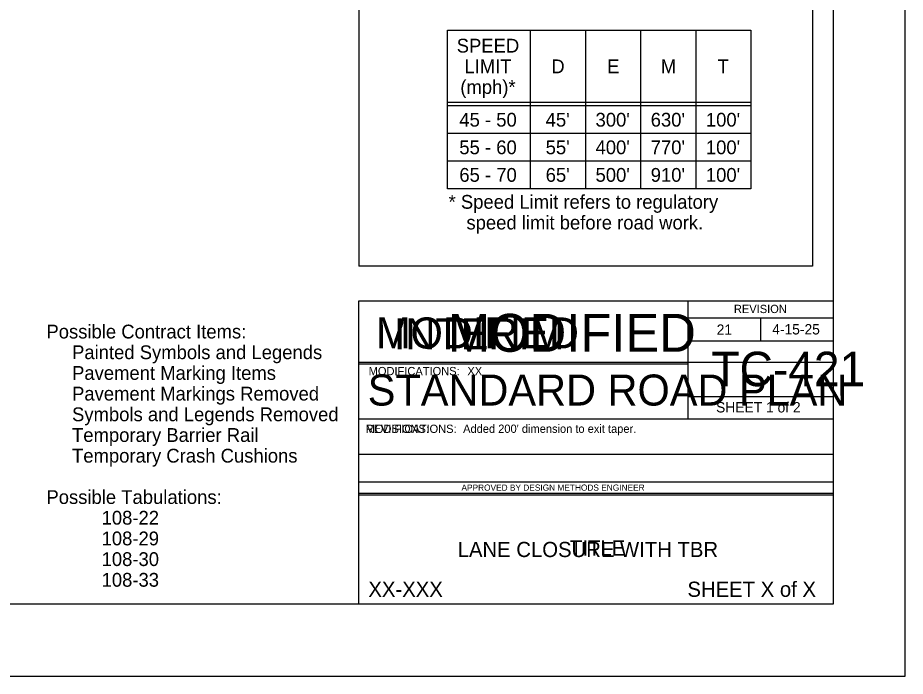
# Model space of a CAD drawing. Extents: x -2135039 to 114557, y -2139150 to -409929.
# Drawn here: x -2132982 to -2131695, y -2139150 to -2138196 of the extents above; entities that cross this region are included whole.
import ezdxf

# ---------------------------------------------------------------- set-up
doc = ezdxf.new("R2010")
doc.units = 0
for name, color, linetype in [('dsnDOTLogo', 7, 'Continuous'), ('dsnNonPlotable', 7, 'Continuous'), ('dsnStdBlock', 7, 'Continuous'), ('dsnstdblockInterim', 7, 'Continuous'), ('dsnStdLogo', 7, 'Continuous'), ('dsnstdModifiedBlock', 7, 'Continuous'), ('dsnStdTable', 7, 'Continuous'), ('Level 1', 7, 'Continuous'), ('StdNote', 7, 'Continuous')]:
    doc.layers.add(name, color=color, linetype=linetype)

msp = doc.modelspace()

# ---------------------------------------------------------------- linework, layer by layer
at = {"layer": 'dsnDOTLogo'}
msp.add_lwpolyline([(-2135038.9, -2139150.4), (-2131694.9, -2139150.4), (-2131694.9, -2136566.4), (-2135038.9, -2136566.4)], close=True, dxfattribs=at)
at = {"layer": 'dsnNonPlotable'}
for p, q in [((-2132487.5, -2137085.9), (-2132487.5, -2138555.9)), ((-2131829.4, -2137085.9), (-2131829.4, -2138555.9)), ((-2131829.4, -2138555.9), (-2132487.5, -2138555.9))]:
    msp.add_line(p, q, dxfattribs=at)
at = {"layer": 'dsnStdLogo'}
for p, q in [((-2132010.4, -2138605.9), (-2132010.4, -2138697.3)), ((-2132010.4, -2138630.9), (-2131799.4, -2138630.9)), ((-2131904.9, -2138630.9), (-2131904.9, -2138664.1)), ((-2132010.4, -2138664.1), (-2131799.4, -2138664.1)), ((-2132487.5, -2138697.3), (-2132010.4, -2138697.3)), ((-2132010.4, -2138697.3), (-2132010.4, -2138777.3)), ((-2131799.4, -2138745.1), (-2132010.4, -2138745.1)), ((-2132487.5, -2138777.3), (-2131799.4, -2138777.3)), ((-2132487.5, -2138828.3), (-2131799.4, -2138828.3)), ((-2132487.5, -2138868.3), (-2131799.4, -2138868.3)), ((-2132487.5, -2138887.3), (-2131799.4, -2138887.3))]:
    msp.add_line(p, q, dxfattribs=at)
msp.add_lwpolyline([(-2132487.5, -2138605.9), (-2131799.4, -2138605.9), (-2131799.4, -2139045.9), (-2132487.5, -2139045.9)], close=True, dxfattribs=at)
at = {"layer": 'dsnstdModifiedBlock'}
for p, q in [((-2132487.5, -2138695), (-2131799.4, -2138695)), ((-2132487.5, -2138885), (-2131799.4, -2138885))]:
    msp.add_line(p, q, dxfattribs=at)
msp.add_lwpolyline([(-2132487.5, -2138605.9), (-2131799.4, -2138605.9), (-2131799.4, -2139045.9), (-2132487.5, -2139045.9)], close=True, dxfattribs=at)
at = {"layer": 'dsnStdTable'}
for p, q in [((-2132358.8, -2138443.4), (-2132358.8, -2138213.6)), ((-2132358.8, -2138213.6), (-2131918.8, -2138213.6)), ((-2132238.8, -2138213.6), (-2132238.8, -2138443.4)), ((-2132158.8, -2138213.6), (-2132158.8, -2138443.4)), ((-2132078.8, -2138213.6), (-2132078.8, -2138443.4)), ((-2131998.8, -2138213.6), (-2131998.8, -2138443.4)), ((-2131918.8, -2138213.6), (-2131918.8, -2138443.4)), ((-2131918.8, -2138318.4), (-2132358.8, -2138318.4)), ((-2131918.8, -2138323.4), (-2132358.8, -2138323.4)), ((-2131918.8, -2138363.4), (-2132358.8, -2138363.4)), ((-2131918.8, -2138403.4), (-2132358.8, -2138403.4)), ((-2131918.8, -2138443.4), (-2132358.8, -2138443.4))]:
    msp.add_line(p, q, dxfattribs=at)
at = {"layer": 'Level 1'}
msp.add_lwpolyline([(-2134934.4, -2137035.9), (-2131799.4, -2137035.9), (-2131799.4, -2139045.9), (-2134934.4, -2139045.9)], close=True, dxfattribs=at)

# ---------------------------------------------------------------- texts
at = {"layer": 'dsnNonPlotable'}
msp.add_text('REVISIONS:', height=12, dxfattribs=at).set_placement((-2132477.5, -2138797.6))
at = {"layer": 'dsnStdBlock'}
for s, height, p in [('MODIFIED', 45, (-2132462.4, -2138675.1)), ('MODIFICATIONS:', 12, (-2132477.5, -2138797.6))]:
    msp.add_text(s, height=height, dxfattribs=at).set_placement(p)
at = {"layer": 'dsnstdblockInterim'}
msp.add_text('INTERIM', height=45, dxfattribs=at).set_placement((-2132436.5, -2138676.3))
at = {"layer": 'dsnStdLogo'}
for s, height, p in [('REVISION', 12, (-2131943.4, -2138623.8)), ('21', 15, (-2131968.4, -2138655.3)), ('4-15-25', 15, (-2131887.9, -2138654.8)), ('TC-421', 50, (-2131976, -2138729.8)), ('STANDARD ROAD PLAN', 45.001, (-2132474.4, -2138757.9)), ('SHEET 1 of 2', 15, (-2131969.3, -2138767.9)), ("Added 200' dimension to exit taper.", 12, (-2132336.1, -2138797.5)), ('APPROVED BY DESIGN METHODS ENGINEER', 9.003, (-2132338.5, -2138881.4)), ('LANE CLOSURE WITH TBR', 22, (-2132344, -2138977.6))]:
    msp.add_text(s, height=height, dxfattribs=at).set_placement(p)
at = {"layer": 'dsnstdModifiedBlock'}
for s, height, p in [('MODIFIED', 55, (-2132358.1, -2138679.9)), ('MODIFICATIONS:', 12, (-2132473.1, -2138713.9)), ('XX', 12, (-2132329.9, -2138713.9)), ('TITLE', 22, (-2132181.1, -2138975.4)), ('XX-XXX', 22, (-2132473.5, -2139035.3)), ('SHEET X of X', 22, (-2132010.8, -2139035.3))]:
    msp.add_text(s, height=height, dxfattribs=at).set_placement(p)
at = {"layer": 'dsnStdTable'}
for s, p in [('SPEED', (-2132345.4, -2138246)), ('LIMIT', (-2132334.2, -2138276)), ('D', (-2132208.2, -2138276)), ('E', (-2132127.4, -2138276)), ('M', (-2132049.4, -2138276)), ('T', (-2131967.1, -2138276)), ('(mph)*', (-2132340.2, -2138306)), ('45 - 50', (-2132341.6, -2138353.4)), ("45'", (-2132216.4, -2138353.4)), ("300'", (-2132144.1, -2138353.4)), ("630'", (-2132064.1, -2138353.4)), ("100'", (-2131984.1, -2138353.4)), ('55 - 60', (-2132341.6, -2138393.4)), ("55'", (-2132216.4, -2138393.4)), ("400'", (-2132144.1, -2138393.4)), ("770'", (-2132064.1, -2138393.4)), ("100'", (-2131984.1, -2138393.4)), ('65 - 70', (-2132341.6, -2138433.4)), ("65'", (-2132216.4, -2138433.4)), ("500'", (-2132144.1, -2138433.4)), ("910'", (-2132064.1, -2138433.4)), ("100'", (-2131984.1, -2138433.4)), ('* Speed Limit refers to regulatory ', (-2132357.2, -2138472.5)), ('speed limit before road work.', (-2132331.3, -2138502.5))]:
    msp.add_text(s, height=20, dxfattribs=at).set_placement(p)
at = {"layer": 'StdNote'}
for s, p in [('Possible Contract Items:', (-2132940.4, -2138660.6)), ('     Painted Symbols and Legends', (-2132940.4, -2138690.6)), ('     Pavement Marking Items', (-2132940.4, -2138720.6)), ('     Pavement Markings Removed', (-2132940.4, -2138750.6)), ('     Symbols and Legends Removed', (-2132940.4, -2138780.6)), ('     Temporary Barrier Rail', (-2132940.4, -2138810.6)), ('     Temporary Crash Cushions', (-2132940.4, -2138840.6)), ('Possible Tabulations:', (-2132940.4, -2138900.6)), ('108-22', (-2132860.4, -2138930.6)), ('108-29', (-2132860.4, -2138960.6)), ('108-30', (-2132860.4, -2138990.6)), ('108-33', (-2132860.4, -2139020.6))]:
    msp.add_text(s, height=20, dxfattribs=at).set_placement(p)

doc.saveas('drawing.dxf')
